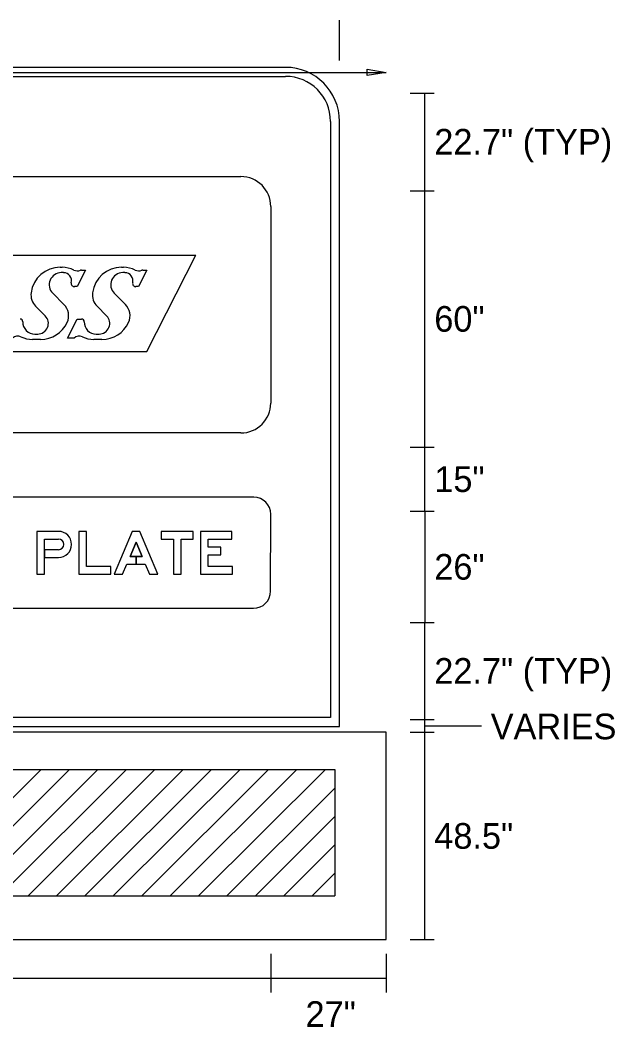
# Model space of a CAD drawing. Extents: x 10268312 to 10268706, y 2142548 to 2142786.
# Drawn here: x 10268450.13 to 10268466.5, y 2142751.92 to 2142779.62 of the extents above; entities that cross this region are included whole.
import ezdxf

# ---------------------------------------------------------------- set-up
doc = ezdxf.new("R2010")
doc.units = 0
for name, color, linetype in [('GSBWFill', 7, 'Continuous'), ('GSDims', 7, 'Continuous'), ('SignPanel', 7, 'Continuous'), ('TextMisc', 7, 'Continuous')]:
    doc.layers.add(name, color=color, linetype=linetype)

msp = doc.modelspace()

# ---------------------------------------------------------------- linework, layer by layer
at = {"layer": 'GSBWFill'}
for p, q in [((10268458.924, 2142778.502), (10268458.924, 2142779.616)), ((10268457.439, 2142778.317), (10268433.672, 2142778.317)), ((10268433.672, 2142778.069), (10268457.439, 2142778.069)), ((10268458.676, 2142776.831), (10268458.676, 2142760.43))]:
    msp.add_line(p, q, dxfattribs=at)
msp.add_lwpolyline([(10268458.676, 2142760.43), (10268432.441, 2142760.43), (10268432.441, 2142760.182), (10268458.924, 2142760.182), (10268458.924, 2142760.182), (10268458.924, 2142776.831)], dxfattribs=at)
for radius in [1.485, 1.238]:
    msp.add_arc((10268457.439, 2142776.831), radius, 0, 90, dxfattribs=at)
at = {"layer": 'GSDims'}
for p, q in [((10268434.809, 2142778.177), (10268460.21, 2142778.177)), ((10268460.871, 2142777.605), (10268461.533, 2142777.605)), ((10268461.268, 2142774.935), (10268461.268, 2142777.605)), ((10268461.533, 2142777.605), (10268461.533, 2142777.605)), ((10268460.871, 2142774.923), (10268461.533, 2142774.923)), ((10268461.268, 2142767.869), (10268461.268, 2142774.935)), ((10268460.871, 2142767.869), (10268461.533, 2142767.869)), ((10268461.268, 2142766.104), (10268461.268, 2142767.869)), ((10268460.871, 2142766.104), (10268461.533, 2142766.104)), ((10268461.268, 2142766.104), (10268461.268, 2142763.046)), ((10268460.871, 2142763.046), (10268461.533, 2142763.046)), ((10268461.268, 2142760.377), (10268461.268, 2142763.046)), ((10268460.871, 2142760.377), (10268461.533, 2142760.377)), ((10268461.268, 2142760.024), (10268461.268, 2142760.377)), ((10268460.871, 2142760.024), (10268461.533, 2142760.024)), ((10268461.268, 2142760.2), (10268462.829, 2142760.2)), ((10268461.268, 2142754.321), (10268461.268, 2142760.024)), ((10268460.871, 2142754.321), (10268461.533, 2142754.321)), ((10268457.035, 2142753.924), (10268457.035, 2142752.865)), ((10268460.21, 2142753.924), (10268460.21, 2142752.865)), ((10268437.984, 2142753.262), (10268457.035, 2142753.262)), ((10268457.035, 2142753.262), (10268460.21, 2142753.262))]:
    msp.add_line(p, q, dxfattribs=at)
msp.add_lwpolyline([(10268460.21, 2142778.177), (10268459.681, 2142778.089), (10268459.681, 2142778.265)], close=True, dxfattribs=at)
at = {"layer": 'SignPanel'}
for p, q in [((10268438.809, 2142775.312), (10268456.209, 2142775.312)), ((10268457.032, 2142774.489), (10268457.032, 2142769.081)), ((10268446.586, 2142773.146), (10268454.969, 2142773.146)), ((10268453.621, 2142770.5), (10268454.969, 2142773.146)), ((10268451.236, 2142772.815), (10268451.291, 2142772.815)), ((10268451.935, 2142772.741), (10268451.701, 2142772.283)), ((10268451.825, 2142772.741), (10268451.935, 2142772.741)), ((10268452.926, 2142772.815), (10268452.982, 2142772.815)), ((10268453.625, 2142772.741), (10268453.391, 2142772.283)), ((10268453.515, 2142772.741), (10268453.625, 2142772.741)), ((10268451.329, 2142772.668), (10268451.266, 2142772.668)), ((10268453.019, 2142772.668), (10268452.956, 2142772.668)), ((10268451.701, 2142772.283), (10268451.628, 2142772.283)), ((10268453.391, 2142772.283), (10268453.318, 2142772.283)), ((10268451.032, 2142772.104), (10268451.34, 2142771.796)), ((10268452.722, 2142772.104), (10268453.03, 2142771.796)), ((10268450.824, 2142771.48), (10268450.56, 2142771.744)), ((10268452.514, 2142771.48), (10268452.25, 2142771.744)), ((10268451.438, 2142770.868), (10268451.705, 2142771.392)), ((10268451.705, 2142771.392), (10268451.823, 2142771.392)), ((10268450.696, 2142770.831), (10268450.475, 2142770.831)), ((10268450.537, 2142770.978), (10268450.617, 2142770.978)), ((10268451.617, 2142770.868), (10268451.438, 2142770.868)), ((10268452.386, 2142770.831), (10268452.164, 2142770.831)), ((10268452.227, 2142770.978), (10268452.307, 2142770.978)), ((10268446.391, 2142770.5), (10268453.621, 2142770.5)), ((10268456.209, 2142768.258), (10268438.809, 2142768.258)), ((10268456.562, 2142766.492), (10268438.457, 2142766.492)), ((10268457.028, 2142763.905), (10268457.032, 2142766.021)), ((10268450.808, 2142765.339), (10268451.19, 2142765.339)), ((10268450.808, 2142765.339), (10268451.19, 2142765.339)), ((10268450.808, 2142765.339), (10268451.19, 2142765.339)), ((10268450.808, 2142764.834), (10268451.19, 2142764.834)), ((10268438.457, 2142763.434), (10268456.558, 2142763.434)), ((10268460.21, 2142760.024), (10268434.809, 2142760.024)), ((10268460.21, 2142754.321), (10268460.21, 2142760.024)), ((10268434.809, 2142754.321), (10268460.21, 2142754.321))]:
    msp.add_line(p, q, dxfattribs=at)
for points in [[(10268451.19, 2142765.551), (10268450.596, 2142765.551), (10268450.596, 2142764.375), (10268450.808, 2142764.375), (10268450.808, 2142764.834)], [(10268451.19, 2142765.551), (10268450.596, 2142765.551), (10268450.596, 2142764.375), (10268450.808, 2142764.375), (10268450.808, 2142765.339)], [(10268451.19, 2142765.551), (10268450.596, 2142765.551), (10268450.596, 2142764.375), (10268450.808, 2142764.375), (10268450.808, 2142765.339)], [(10268451.19, 2142765.045), (10268450.808, 2142765.045), (10268450.808, 2142765.339)], [(10268451.19, 2142765.045), (10268450.808, 2142765.045), (10268450.808, 2142764.834), (10268451.19, 2142764.834)], [(10268451.19, 2142765.045), (10268450.808, 2142765.045), (10268450.808, 2142764.834), (10268451.19, 2142764.834)]]:
    msp.add_lwpolyline(points, dxfattribs=at)
for points in [[(10268452.631, 2142764.375), (10268452.631, 2142764.581), (10268451.96, 2142764.581), (10268451.96, 2142765.551), (10268451.749, 2142765.551), (10268451.749, 2142764.375)], [(10268452.631, 2142764.375), (10268452.631, 2142764.581), (10268451.96, 2142764.581), (10268451.96, 2142765.551), (10268451.749, 2142765.551), (10268451.749, 2142764.375)], [(10268452.631, 2142764.375), (10268452.631, 2142764.581), (10268451.96, 2142764.581), (10268451.96, 2142765.551), (10268451.749, 2142765.551), (10268451.749, 2142764.375)], [(10268453.07, 2142764.651), (10268453.578, 2142764.651), (10268453.695, 2142764.375), (10268453.924, 2142764.375), (10268453.43, 2142765.551), (10268453.219, 2142765.551), (10268452.725, 2142764.375), (10268452.954, 2142764.375)], [(10268453.49, 2142764.863), (10268453.324, 2142764.863), (10268453.324, 2142764.651), (10268453.578, 2142764.651), (10268453.695, 2142764.375), (10268453.924, 2142764.375), (10268453.43, 2142765.551), (10268453.219, 2142765.551), (10268452.725, 2142764.375), (10268452.954, 2142764.375), (10268453.07, 2142764.651), (10268453.324, 2142764.651), (10268453.324, 2142764.863), (10268453.159, 2142764.863), (10268453.324, 2142765.256)], [(10268453.49, 2142764.863), (10268453.324, 2142764.863), (10268453.324, 2142764.651), (10268453.578, 2142764.651), (10268453.695, 2142764.375), (10268453.924, 2142764.375), (10268453.43, 2142765.551), (10268453.219, 2142765.551), (10268452.725, 2142764.375), (10268452.954, 2142764.375), (10268453.07, 2142764.651), (10268453.324, 2142764.651), (10268453.324, 2142764.863), (10268453.159, 2142764.863), (10268453.324, 2142765.256)], [(10268454.018, 2142765.339), (10268454.353, 2142765.339), (10268454.353, 2142764.375), (10268454.565, 2142764.375), (10268454.565, 2142765.339), (10268454.9, 2142765.339), (10268454.9, 2142765.551), (10268454.018, 2142765.551)], [(10268454.018, 2142765.339), (10268454.353, 2142765.339), (10268454.353, 2142764.375), (10268454.565, 2142764.375), (10268454.565, 2142765.339), (10268454.9, 2142765.339), (10268454.9, 2142765.551), (10268454.018, 2142765.551)], [(10268454.018, 2142765.339), (10268454.353, 2142765.339), (10268454.353, 2142764.375), (10268454.565, 2142764.375), (10268454.565, 2142765.339), (10268454.9, 2142765.339), (10268454.9, 2142765.551), (10268454.018, 2142765.551)], [(10268455.982, 2142764.587), (10268455.312, 2142764.587), (10268455.312, 2142764.903), (10268455.659, 2142764.903), (10268455.659, 2142765.115), (10268455.312, 2142765.115), (10268455.312, 2142765.339), (10268455.964, 2142765.339), (10268455.964, 2142765.551), (10268455.1, 2142765.551), (10268455.1, 2142764.375), (10268455.982, 2142764.375)], [(10268455.982, 2142764.587), (10268455.312, 2142764.587), (10268455.312, 2142764.903), (10268455.659, 2142764.903), (10268455.659, 2142765.115), (10268455.312, 2142765.115), (10268455.312, 2142765.339), (10268455.964, 2142765.339), (10268455.964, 2142765.551), (10268455.1, 2142765.551), (10268455.1, 2142764.375), (10268455.982, 2142764.375)], [(10268455.982, 2142764.587), (10268455.312, 2142764.587), (10268455.312, 2142764.903), (10268455.659, 2142764.903), (10268455.659, 2142765.115), (10268455.312, 2142765.115), (10268455.312, 2142765.339), (10268455.964, 2142765.339), (10268455.964, 2142765.551), (10268455.1, 2142765.551), (10268455.1, 2142764.375), (10268455.982, 2142764.375)], [(10268453.49, 2142764.863), (10268453.324, 2142765.256), (10268453.159, 2142764.863)]]:
    msp.add_lwpolyline(points, close=True, dxfattribs=at)
for centre, radius, start, end in [((10268456.209, 2142774.489), 0.823, 0, 90), ((10268451.236, 2142772.007), 0.808, 90, 172.3089), ((10268451.291, 2142772.08), 0.735, 64.0896, 90), ((10268451.709, 2142772.939), 0.22, 244.0896, 292.0347), ((10268451.825, 2142772.653), 0.0882, 90, 112.0347), ((10268452.926, 2142772.007), 0.808, 90, 172.3089), ((10268452.981, 2142772.08), 0.735, 64.0896, 90), ((10268453.399, 2142772.939), 0.22, 244.0896, 292.0347), ((10268453.515, 2142772.653), 0.0882, 90, 112.0347), ((10268451.266, 2142772.337), 0.331, 90, 225), ((10268451.329, 2142772.447), 0.22, 345.6915, 90), ((10268452.956, 2142772.337), 0.331, 90, 225), ((10268453.019, 2142772.447), 0.22, 345.6915, 90), ((10268451.628, 2142772.371), 0.0882, 165.6915, 270), ((10268453.318, 2142772.371), 0.0882, 165.6915, 270), ((10268450.872, 2142772.056), 0.441, 172.3089, 225), ((10268452.562, 2142772.056), 0.441, 172.3089, 225), ((10268451.028, 2142771.484), 0.441, 334.95, 45), ((10268452.718, 2142771.484), 0.441, 334.95, 45), ((10268450.133, 2142771.318), 0.0735, 358.6664, 90), ((10268450.537, 2142771.309), 0.331, 178.6665, 270), ((10268450.616, 2142771.272), 0.294, 270, 45), ((10268451.823, 2142771.318), 0.0735, 358.6664, 90), ((10268452.227, 2142771.309), 0.331, 178.6665, 270), ((10268452.306, 2142771.272), 0.294, 270, 45), ((10268450.695, 2142771.639), 0.808, 270, 334.95), ((10268452.385, 2142771.639), 0.808, 270, 334.95), ((10268450.068, 2142770.718), 0.206, 64.3795, 133.1892), ((10268450.474, 2142771.566), 0.735, 244.3795, 270), ((10268451.758, 2142770.718), 0.206, 64.3795, 133.1892), ((10268452.164, 2142771.566), 0.735, 244.3795, 270), ((10268456.209, 2142769.081), 0.823, 270, 360), ((10268456.562, 2142766.021), 0.47, 0, 90), ((10268451.19, 2142765.192), 0.359, 270, 90), ((10268451.19, 2142765.192), 0.359, 270, 90), ((10268451.19, 2142765.192), 0.359, 270, 90), ((10268451.19, 2142765.192), 0.147, 270, 90), ((10268451.19, 2142765.192), 0.147, 270, 90), ((10268451.19, 2142765.192), 0.147, 270, 90), ((10268456.558, 2142763.905), 0.47, 270, 0)]:
    msp.add_arc(centre, radius, start, end, dxfattribs=at)
at = {"layer": 'TextMisc'}
for p, q in [((10268436.22, 2142759.002), (10268458.799, 2142759.002)), ((10268447.22, 2142755.519), (10268450.711, 2142759.002)), ((10268448.003, 2142755.519), (10268451.493, 2142759.002)), ((10268448.785, 2142755.519), (10268452.276, 2142759.002)), ((10268449.567, 2142755.519), (10268453.058, 2142759.002)), ((10268450.35, 2142755.519), (10268453.84, 2142759.002)), ((10268451.132, 2142755.519), (10268454.623, 2142759.002)), ((10268451.914, 2142755.519), (10268455.405, 2142759.002)), ((10268452.697, 2142755.519), (10268456.187, 2142759.002)), ((10268453.479, 2142755.519), (10268456.97, 2142759.002)), ((10268454.261, 2142755.519), (10268457.752, 2142759.002)), ((10268455.044, 2142755.519), (10268458.534, 2142759.002)), ((10268458.799, 2142759.002), (10268458.799, 2142755.519)), ((10268455.826, 2142755.519), (10268458.799, 2142758.485)), ((10268456.608, 2142755.519), (10268458.799, 2142757.704)), ((10268457.39, 2142755.519), (10268458.799, 2142756.924)), ((10268458.173, 2142755.519), (10268458.799, 2142756.143)), ((10268436.22, 2142755.519), (10268458.799, 2142755.519))]:
    msp.add_line(p, q, dxfattribs=at)

# ---------------------------------------------------------------- texts
at = {"layer": 'GSDims'}
for s, height, p in [('22.7" (TYP)', 0.70558, (10268461.533, 2142775.917)), ('60"', 0.7056, (10268461.533, 2142771.044)), ('15"', 0.7056, (10268461.533, 2142766.634)), ('26"', 0.7056, (10268461.533, 2142764.222)), ('22.7" (TYP)', 0.70558, (10268461.533, 2142761.359)), ('VARIES', 0.7056, (10268463.086, 2142759.831)), ('48.5"', 0.7056, (10268461.533, 2142756.819)), ('27"', 0.7056, (10268457.989, 2142751.918))]:
    msp.add_text(s, height=height, dxfattribs=at).set_placement(p)

doc.saveas('drawing.dxf')
